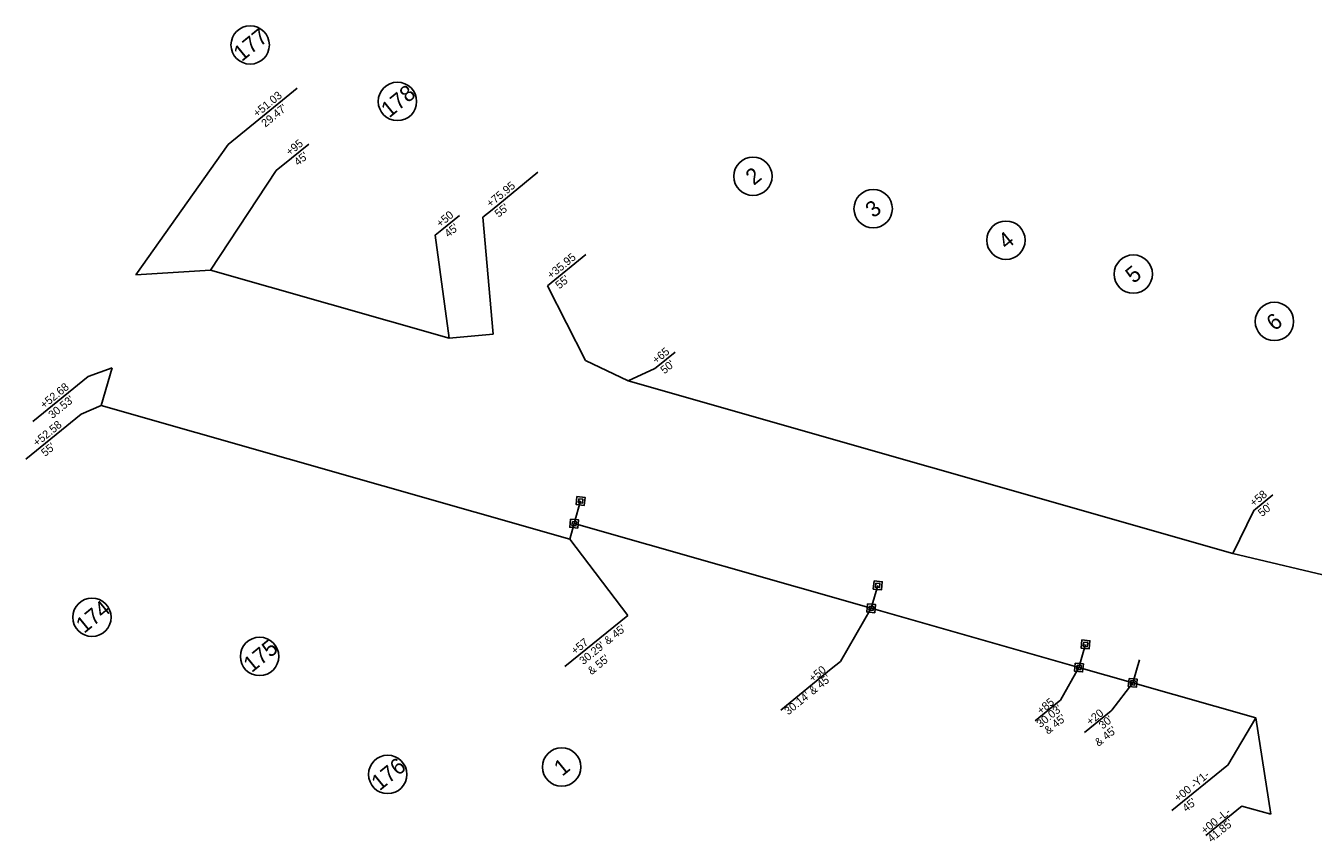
# Model space of a CAD drawing. Extents: x 2320946 to 2332748, y 597838 to 612698.
# Drawn here: x 2320946 to 2321750, y 598087 to 598596 of the extents above; entities that cross this region are included whole.
import ezdxf

# ---------------------------------------------------------------- set-up
doc = ezdxf.new("R2010")
doc.units = 0
for name, color, linetype in [('Prop Easement Construction', 7, 'Continuous'), ('Prop Easement Construction Station Offsets', 7, 'Continuous'), ('Prop Easement Permanent Drainage', 7, 'Continuous'), ('Prop Easement Permanent Drainage Station Offsets', 7, 'Continuous'), ('Prop Easement Permanent Drainage Utility', 7, 'Continuous'), ('Prop Easement Permanent Drainage Utility Station Offsets', 7, 'Continuous'), ('Prop Parcel Number CELL', 7, 'Continuous'), ('Prop ROW Marker CELL', 7, 'Continuous'), ('Prop ROW Permanent Easement CELL', 7, 'Continuous')]:
    doc.layers.add(name, color=color, linetype=linetype)

msp = doc.modelspace()

# ---------------------------------------------------------------- linework, layer by layer
at = {"layer": 'Prop Easement Construction'}
for p, q in [((2321014.6, 598440.76), (2321061.15, 598443.64)), ((2321061.15, 598443.64), (2321210.21, 598401.15)), ((2321210.21, 598401.15), (2321237.9, 598403.65)), ((2321295.61, 598387.2), (2321322.17, 598374.43)), ((2320992.94, 598359.1), (2320999.75, 598382.6)), ((2321322.17, 598374.43), (2321700.12, 598266.69)), ((2320992.94, 598359.1), (2321285.7, 598275.65)), ((2321288.44, 598285.26), (2321285.7, 598275.65)), ((2321700.12, 598266.69), (2321823.28, 598237.14)), ((2321637.53, 598185.75), (2321714.47, 598163.82)), ((2321723.73, 598103.65), (2321714.47, 598163.82))]:
    msp.add_line(p, q, dxfattribs=at)
at = {"layer": 'Prop Easement Construction Station Offsets'}
for p, q in [((2321115.24, 598557.37), (2321091.31, 598537.83)), ((2321122.56, 598522.56), (2321111.72, 598513.7)), ((2321265.81, 598504.89), (2321237.1, 598481.45)), ((2321216.7, 598477.93), (2321205.73, 598468.98)), ((2321295.76, 598453.48), (2321271.83, 598433.94)), ((2321271.83, 598433.94), (2321295.61, 598387.2)), ((2321351.55, 598392.48), (2321340.7, 598383.62)), ((2320984.74, 598377.27), (2320950.2, 598349.08)), ((2320980.24, 598353.65), (2320945.71, 598325.46)), ((2321725.04, 598303.24), (2321714.13, 598294.34)), ((2321321.96, 598227.91), (2321285.7, 598275.65)), ((2321321.96, 598227.91), (2321282.7, 598195.86)), ((2321696.22, 598133.82), (2321661.96, 598105.85)), ((2321704.79, 598107.94), (2321683.08, 598090.22))]:
    msp.add_line(p, q, dxfattribs=at)
for points in [[(2321091.31, 598537.83), (2321072.17, 598522.2), (2321014.6, 598440.76)], [(2321111.72, 598513.7), (2321102.25, 598505.97), (2321061.15, 598443.64)], [(2321237.1, 598481.45), (2321231.39, 598476.79), (2321237.9, 598403.65)], [(2321205.73, 598468.98), (2321201.64, 598465.64), (2321210.21, 598401.15)], [(2320984.74, 598377.27), (2320999.75, 598382.6)], [(2321340.7, 598383.62), (2321338.9, 598382.15), (2321322.17, 598374.43)], [(2320980.24, 598353.65), (2320992.94, 598359.1)], [(2321714.13, 598294.34), (2321713.1, 598293.49), (2321700.12, 598266.69)], [(2321696.22, 598133.82), (2321696.86, 598134.34), (2321714.47, 598163.82)], [(2321704.79, 598107.94), (2321705.63, 598108.62), (2321723.73, 598103.65)]]:
    msp.add_lwpolyline(points, dxfattribs=at)
at = {"layer": 'Prop Easement Permanent Drainage'}
for p, q in [((2321292.47, 598299.41), (2321288.44, 598285.26)), ((2321288.44, 598285.26), (2321474.04, 598232.35)), ((2321637.53, 598185.75), (2321641.64, 598200.18)), ((2321603.87, 598195.35), (2321637.53, 598185.75))]:
    msp.add_line(p, q, dxfattribs=at)
at = {"layer": 'Prop Easement Permanent Drainage Station Offsets'}
msp.add_line((2321623.98, 598168.24), (2321607.29, 598154.77), dxfattribs=at)
msp.add_lwpolyline([(2321623.98, 598168.24), (2321624.51, 598168.6), (2321637.53, 598185.75)], dxfattribs=at)
at = {"layer": 'Prop Easement Permanent Drainage Utility'}
msp.add_line((2321474.04, 598232.35), (2321603.87, 598195.35), dxfattribs=at)
at = {"layer": 'Prop Easement Permanent Drainage Utility Station Offsets'}
for p, q in [((2321474.04, 598232.35), (2321478.12, 598246.65)), ((2321607.98, 598209.74), (2321603.87, 598195.35)), ((2321449.12, 598194.53), (2321417.53, 598168.74)), ((2321591.58, 598174.24), (2321576.56, 598161.98))]:
    msp.add_line(p, q, dxfattribs=at)
for points in [[(2321449.12, 598194.53), (2321454.79, 598199.16), (2321474.04, 598232.35)], [(2321591.58, 598174.24), (2321592.42, 598174.93), (2321603.87, 598195.35)]]:
    msp.add_lwpolyline(points, dxfattribs=at)
at = {"layer": 'Prop Parcel Number CELL'}
for p, q in [((2321085.96, 598584.49), (2321085.96, 598584.49)), ((2321177.98, 598549.15), (2321177.98, 598549.15)), ((2321400.17, 598502.37), (2321400.17, 598502.37)), ((2321475.27, 598482.14), (2321475.27, 598482.14)), ((2321558.26, 598462.43), (2321558.26, 598462.43)), ((2321637.82, 598441.23), (2321637.82, 598441.23)), ((2321726.06, 598411.63), (2321726.06, 598411.63)), ((2320987.07, 598226.71), (2320987.07, 598226.71)), ((2321091.82, 598202.24), (2321091.82, 598202.24)), ((2321171.92, 598128.47), (2321171.92, 598128.47)), ((2321280.61, 598133.13), (2321280.61, 598133.13))]:
    msp.add_line(p, q, dxfattribs=at)
for centre in [(2321085.96, 598584.49), (2321177.98, 598549.15), (2321400.17, 598502.37), (2321475.27, 598482.14), (2321558.26, 598462.43), (2321637.82, 598441.23), (2321726.06, 598411.63), (2320987.07, 598226.71), (2321091.82, 598202.24), (2321280.61, 598133.13), (2321171.92, 598128.47)]:
    msp.add_circle(centre, 12, dxfattribs=at)
at = {"layer": 'Prop ROW Marker CELL'}
for p, q in [((2321292.47, 598299.41), (2321292.47, 598299.41)), ((2321288.44, 598285.26), (2321288.44, 598285.26)), ((2321478.12, 598246.65), (2321478.12, 598246.65)), ((2321474.04, 598232.35), (2321474.04, 598232.35)), ((2321607.98, 598209.74), (2321607.98, 598209.74)), ((2321603.87, 598195.35), (2321603.87, 598195.35)), ((2321637.53, 598185.75), (2321637.53, 598185.75))]:
    msp.add_line(p, q, dxfattribs=at)
at = {"layer": 'Prop ROW Permanent Easement CELL'}
for points in [[(2321290.19, 598302.2), (2321295.26, 598301.69), (2321294.75, 598296.62), (2321289.68, 598297.13)], [(2321291.33, 598300.81), (2321293.86, 598300.55), (2321293.61, 598298.02), (2321291.08, 598298.27)], [(2321286.16, 598288.05), (2321291.23, 598287.54), (2321290.71, 598282.48), (2321285.65, 598282.99)], [(2321287.3, 598286.66), (2321289.83, 598286.4), (2321289.57, 598283.87), (2321287.04, 598284.13)], [(2321475.84, 598249.44), (2321480.91, 598248.93), (2321480.39, 598243.86), (2321475.33, 598244.37)], [(2321476.98, 598248.04), (2321479.51, 598247.79), (2321479.26, 598245.26), (2321476.72, 598245.51)], [(2321471.77, 598235.14), (2321476.83, 598234.63), (2321476.32, 598229.57), (2321471.25, 598230.08)], [(2321472.9, 598233.75), (2321475.44, 598233.49), (2321475.18, 598230.96), (2321472.65, 598231.22)], [(2321605.7, 598212.53), (2321610.76, 598212.02), (2321610.25, 598206.96), (2321605.19, 598207.47)], [(2321606.84, 598211.14), (2321609.37, 598210.88), (2321609.11, 598208.35), (2321606.58, 598208.61)], [(2321601.59, 598198.13), (2321606.66, 598197.62), (2321606.15, 598192.56), (2321601.08, 598193.07)], [(2321602.73, 598196.74), (2321605.27, 598196.48), (2321605.01, 598193.95), (2321602.48, 598194.21)], [(2321635.25, 598188.54), (2321640.32, 598188.03), (2321639.81, 598182.96), (2321634.74, 598183.47)], [(2321636.39, 598187.15), (2321638.92, 598186.89), (2321638.67, 598184.36), (2321636.14, 598184.61)]]:
    msp.add_lwpolyline(points, close=True, dxfattribs=at)

# ---------------------------------------------------------------- texts
at = {"layer": 'Prop Easement Construction Station Offsets'}
for s, p in [('+51.03', (2321090.32, 598539.04)), ("29.47'", (2321095.46, 598532.75)), ('+95', (2321110.73, 598514.91)), ("45'", (2321115.87, 598508.62)), ('+75.95', (2321236.11, 598482.66)), ("55'", (2321241.25, 598476.36)), ('+50', (2321204.74, 598470.19)), ("45'", (2321209.88, 598463.9)), ('+35.95', (2321274.03, 598437.93)), ("55'", (2321279.17, 598431.63)), ('+65', (2321339.71, 598384.83)), ("50'", (2321344.85, 598378.54)), ('+52.68', (2320957.2, 598356.81)), ("30.53'", (2320962.34, 598350.51)), ('+52.58', (2320952.71, 598333.19)), ("55'", (2320957.84, 598326.9)), ('+58', (2321713.14, 598295.55)), ("50'", (2321718.28, 598289.25)), ("30.29' & 45'", (2321294.15, 598196.73)), ('+57', (2321289.01, 598203.03)), ("& 55'", (2321299.29, 598190.44)), ('+00 -Y1-', (2321665.87, 598111.06)), ("45'", (2321671, 598104.76)), ('+00 -L-', (2321682.59, 598090.82)), ("41.85'", (2321686.73, 598085.74))]:
    msp.add_text(s, height=5, rotation=39.22799, dxfattribs=at).set_placement(p)
at = {"layer": 'Prop Easement Permanent Drainage Station Offsets'}
for s, p in [('+20', (2321610.95, 598158.85)), ("30' ", (2321618.75, 598156.47)), ("& 45'", (2321616.15, 598145.69))]:
    msp.add_text(s, height=5, rotation=38.90955, dxfattribs=at).set_placement(p)
at = {"layer": 'Prop Easement Permanent Drainage Utility Station Offsets'}
for s, p in [('+50', (2321437.52, 598185.87)), ("30.14' & 45'", (2321422.29, 598165.37)), ('+85', (2321580.14, 598165.71)), ("30.03'", (2321579.82, 598157.38)), ("& 45'", (2321584.62, 598153.23))]:
    msp.add_text(s, height=5, rotation=39.22799, dxfattribs=at).set_placement(p)
at = {"layer": 'Prop Parcel Number CELL'}
for s, p in [('177', (2321080.68, 598573.72)), ('178', (2321172.88, 598538.53)), ('2', (2321400.69, 598496.34)), ('3', (2321475.54, 598475.91)), ('4', (2321558.57, 598456.23)), ('5', (2321638.07, 598434.98)), ('6', (2321726.18, 598405.28)), ('174', (2320982.18, 598216.27)), ('175', (2321086.88, 598191.74)), ('176', (2321166.84, 598117.87)), ('1', (2321280.95, 598126.95))]:
    msp.add_text(s, height=10, rotation=39.22799, dxfattribs=at).set_placement(p)

doc.saveas('drawing.dxf')
